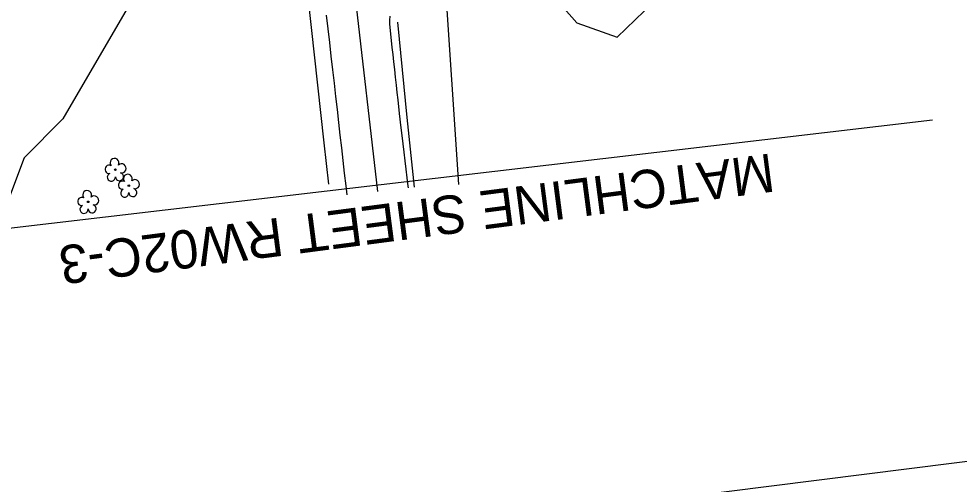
# Model space of a CAD drawing. Extents: x 476627 to 479509, y 495837 to 499842.
# Drawn here: x 478091.3 to 478484, y 496375.9 to 496570.2 of the extents above; entities that cross this region are included whole.
import ezdxf

# ---------------------------------------------------------------- set-up
doc = ezdxf.new("R2010")
doc.units = 0
for name, color, linetype in [('CTL Sheet Border CELL', 7, 'Continuous'), ('Exist Guardrail', 7, 'Continuous'), ('Exist Horizontal Alignment', 7, 'Continuous'), ('Exist Roads EOP', 7, 'Continuous'), ('Exist Vegetation Hedge Row', 7, 'Continuous'), ('Exist Vegetation Tree CELL', 7, 'Continuous'), ('Exist Vegetation Woods Line', 7, 'Continuous'), ('Matchline', 7, 'Continuous'), ('Matchline Text', 7, 'Continuous')]:
    doc.layers.add(name, color=color, linetype=linetype)

msp = doc.modelspace()

# ---------------------------------------------------------------- linework, layer by layer
at = {"layer": 'CTL Sheet Border CELL'}
msp.add_lwpolyline([(476686.29, 499507.12), (477101.06, 496211.1), (479408.26, 496501.44), (478993.48, 499797.47)], close=True, dxfattribs=at)
at = {"layer": 'Exist Guardrail'}
msp.add_lwpolyline([(478249.4, 496568.86), (478253.32, 496529.06), (478256.35, 496499.9)], dxfattribs=at)
at = {"layer": 'Exist Horizontal Alignment'}
msp.add_line((478241.22, 496498.17), (478119.71, 497553.37), dxfattribs=at)
at = {"layer": 'Exist Roads EOP'}
for points in [[(478228.43, 496496.7), (478227.97, 496500.51), (478227.35, 496505.77), (478226.73, 496511.09), (478226.12, 496516.4), (478225.51, 496521.7), (478224.91, 496526.99), (478224.31, 496532.32), (478223.69, 496537.76), (478223.06, 496543.31), (478222.41, 496548.97), (478221.76, 496554.68), (478221.11, 496560.39), (478220.46, 496566.1), (478219.81, 496571.81)], [(478246.26, 496571.37), (478246.08, 496569.68), (478246.08, 496568.05), (478246.62, 496562.59), (478247.1, 496558.25), (478247.41, 496555.37), (478247.75, 496552.23), (478248.1, 496549.05), (478248.45, 496545.84), (478248.81, 496542.59), (478249.16, 496539.4), (478249.5, 496536.34), (478250.16, 496530.64), (478250.85, 496524.78), (478251.23, 496521.54), (478251.64, 496518.08), (478252.07, 496514.52), (478252.49, 496510.97), (478252.92, 496507.42), (478253.35, 496503.87), (478253.77, 496500.32), (478253.85, 496499.67)]]:
    msp.add_lwpolyline(points, dxfattribs=at)
at = {"layer": 'Exist Vegetation Hedge Row'}
msp.add_lwpolyline([(478204.01, 496651.61), (478218.61, 496518.46), (478220.64, 496501.13)], dxfattribs=at)
at = {"layer": 'Exist Vegetation Tree CELL'}
for p, q in [((478131.62, 496507.23), (478131.62, 496507.23)), ((478137.21, 496500.59), (478137.21, 496500.59)), ((478120.22, 496493.8), (478120.22, 496493.8))]:
    msp.add_line(p, q, dxfattribs=at)
for centre in [(478131.62, 496507.23), (478137.21, 496500.59), (478120.22, 496493.8)]:
    msp.add_circle(centre, 0.326, dxfattribs=at)
for centre, radius, start, end in [((478131.23, 496510.1), 1.86, 330.1651, 219.7134), ((478129.01, 496507.38), 1.73, 62.6636, 279.3457), ((478134.17, 496507.82), 1.9, 257.1011, 134.1999), ((478129.91, 496504.11), 1.69, 111.5671, 6.231), ((478133.29, 496504.33), 1.7, 181.2822, 74.56), ((478136.82, 496503.47), 1.86, 330.1651, 219.7134), ((478134.6, 496500.75), 1.73, 62.6636, 279.3457), ((478139.76, 496501.18), 1.9, 257.1011, 134.1999), ((478119.83, 496496.67), 1.86, 330.1651, 219.7134), ((478122.77, 496494.39), 1.9, 257.1011, 134.1999), ((478135.5, 496497.47), 1.69, 111.5671, 6.231), ((478138.88, 496497.69), 1.7, 181.2822, 74.56), ((478117.61, 496493.95), 1.73, 62.6636, 279.3457), ((478118.51, 496490.68), 1.69, 111.5671, 6.231), ((478121.89, 496490.9), 1.7, 181.2822, 74.56)]:
    msp.add_arc(centre, radius, start, end, dxfattribs=at)
at = {"layer": 'Exist Vegetation Woods Line'}
for points in [[(478067.75, 496608.04), (478117.36, 496603.45), (478177.88, 496589.88), (478177.8, 496586.07), (478142.44, 496584.63), (478109.62, 496528.51), (478093.53, 496512.14), (478082.21, 496482.6)], [(478275.03, 496501.06), (478269.24, 496588.78), (478280.93, 496596.29), (478312.46, 496594.29), (478315.77, 496578.25), (478324.29, 496568.51), (478341.22, 496562.61), (478356.13, 496577.03), (478341.76, 496599.15), (478344.52, 496595.39), (478361.67, 496586.74), (478389.14, 496583.27), (478396.92, 496590.28)]]:
    msp.add_lwpolyline(points, dxfattribs=at)
at = {"layer": 'Matchline'}
msp.add_line((478472.84, 496527.98), (477976.24, 496469.75), dxfattribs=at)

# ---------------------------------------------------------------- texts
at = {"layer": 'Matchline Text'}
msp.add_text('MATCHLINE SHEET RW02C-3', height=16, rotation=187.4417, dxfattribs=at).set_placement((478405.57, 496514.1))

doc.saveas('drawing.dxf')
